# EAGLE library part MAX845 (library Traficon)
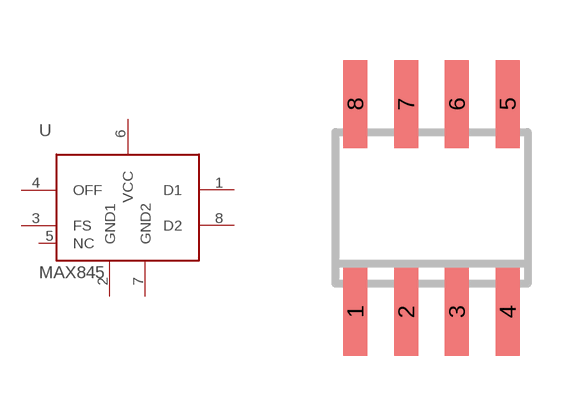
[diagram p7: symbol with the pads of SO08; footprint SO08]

Designator prefix -

## MAX845  [SO08]
1  D1  out
2  GND1  pas
3  FS  in
4  OFF  in
5  NC  pas
6  VCC  pas
7  GND2  pas
8  D2  out

## Footprint SO08 (pad centres in mm)
Small Outline Package
smd 0.6 x 2.2: 1 -1.905,-2.6; 2 -0.635,-2.6; 3 0.635,-2.6; 4 1.905,-2.6; 5 1.905,2.6; 6 0.635,2.6; 7 -0.635,2.6; 8 -1.905,2.6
